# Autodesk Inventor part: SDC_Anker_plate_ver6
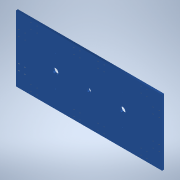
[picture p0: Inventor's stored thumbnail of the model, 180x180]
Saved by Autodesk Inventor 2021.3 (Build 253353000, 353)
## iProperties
Created: 2022-01
Part Number: SDC_Anker_plate_ver6
Material: アルミニウム 6061
Document SubType Name: Modeling
Designer: kengo
Density: 2.7 g/cm^3
Appearance: アルミニウム - フラット
Author: kengo
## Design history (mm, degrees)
sketch "スケッチ1"
  geometry: L1 (-589.671, 316.432)-(590.329, 316.432); L2 (590.329, 316.432)-(590.329, -283.568); L3 (590.329, -283.568)-(-589.671, -283.568); L4 (-589.671, -283.568)-(-589.671, 316.432); 1 further point
  constraints: 8 end point, 2 parallel, 1 horizontal, 1 perpendicular
  dimensions: "d0" = 600 distance of L3.end L1.start; "d1" = 1180 distance of L1.start L1.end
extrude "押し出し1" new body sketch "スケッチ1" distance "d2" = 15; taper "d3" = 0 deg
sketch "スケッチ4"
  geometry: L1 (-589.671, 316.432)-(-589.671, -283.568) reference; L2 (590.329, -283.568)-(590.329, 316.432) reference; L3 (-589.671, 261.432)-(590.329, 261.432); L4 (590.329, 261.432)-(590.329, -228.568); L5 (590.329, -228.568)-(-589.671, -228.568); L6 (-589.671, -228.568)-(-589.671, 261.432); L7 (590.329, 316.432)-(-589.671, 316.432) reference; L8 (-589.671, -283.568)-(590.329, -283.568) reference; L9 (-589.671, 316.432)-(590.329, 316.432); L10 (590.329, 316.432)-(590.329, -283.568); L11 (590.329, -283.568)-(-589.671, -283.568); L12 (-589.671, -283.568)-(-589.671, 316.432); 3 further points
  constraints: 16 end point, 4 parallel, 2 horizontal, 2 perpendicular, 2 point on line
  dimensions: "d58" = 490 distance between parallel lines of L5 L3; "d59" = 55 distance between parallel lines of L7 L3
extrude "押し出し2" cut sketch "スケッチ4" distance "d60" = 30; taper "d61" = 0 deg
sketch "スケッチ3" dims "d34" = 10, "d41" = 10
  geometry: L1 (-590.329, -283.568)-(-590.329, 316.432) reference; L2 (-590.329, 316.432)-(589.671, 316.432) reference; L3 (-590.329, 316.432)-(-180.344, 316.432); L4 (589.671, 261.432)-(-590.329, 261.432) reference; C1 r 3.324 at (-567.829, 228.932) reference; 25 further points
  constraints: 2 end point, 2 horizontal, 2 vertical, 1 point on line, 23 other
  dimensions: "d28" = 22.5 distance from line of L1 point (-567.829, 148.932); "d31" = 45 distance of point (-567.829, 148.932) point (-567.829, 103.932); "d38" = 45 distance of point (-567.829, 103.932) point (-522.829, 103.932); "d45" = 220 distance of point (-522.829, 148.932) point (-522.829, -71.068); "d48" = 1000 distance of point (-522.829, 148.932) point (477.171, 148.932); "d144" = 112.5 distance from line of L4 point (-567.829, 148.932)
hole "穴2" sketch "スケッチ3" diameter "d51" = 6.647; stored, may be unused: countersink angle "d55" = 90 deg, drill point angle "d57" = 118 deg; dims "d52" = 20, "d53" = 4, "d54" = 2, "d56" = 22.2
sketch "スケッチ5" dims "d83" = 10
  geometry: L1 (590.329, 261.432)-(-589.671, 261.432) reference; L2 (-589.671, 261.432)-(-589.671, -283.568) reference; 34 further points
  constraints: 2 horizontal, 1 vertical, 28 other
  dimensions: "d62" = 22.5 distance from line of L1 point (-387.171, 238.932); "d63" = 45 distance of point (-387.171, 193.932) point (-387.171, 238.932); "d64" = 45 distance of point (-342.171, 238.932) point (-342.171, 193.932); "d65" = 22.5 distance from line of L1 point (-342.171, 238.932); "d66" = 45 distance of point (-387.171, 193.932) point (-342.171, 193.932); "d69" = 45 distance of point (-387.171, 238.932) point (-342.171, 238.932); "d72" = 400 distance of point (-342.171, 238.932) point (-342.171, -161.068); "d75" = 320 distance of point (-342.171, 238.932) point (-22.171, 238.932); "d80" = 500 distance of point (-67.171, -161.068) point (432.829, -161.068); "d117" = 202.5 distance from line of L2 point (-387.171, 238.932); "d118" = 202.5 distance from line of L2 point (-387.171, 193.932)
hole "穴3" sketch "スケッチ5" diameter "d85" = 6.647; stored, may be unused: countersink angle "d89" = 90 deg, drill point angle "d91" = 118 deg; dims "d86" = 20, "d87" = 4, "d88" = 2, "d90" = 22.2
sketch "スケッチ7" dims "d101" = 10, "d108" = 10
  geometry: L1 (590.329, 261.432)-(-589.671, 261.432) reference; L2 (-589.671, 261.432)-(-589.671, -228.568) reference; L3 (-589.671, 261.432)-(-589.671, -228.568); C1 r 3.324 at (-342.171, 193.932) reference; 6 further points
  constraints: 2 end point, 1 collinear, 1 horizontal, 1 vertical, 3 other
  dimensions: "d94" = 130 distance from line of L1 point (-204.671, 131.432); "d95" = 137.5 horizontal distance of point (-204.671, 131.432) C1.centre; "d98" = 500 distance of point (-204.671, 131.432) point (295.329, 131.432); "d105" = 230 distance of point (295.329, 131.432) point (295.329, -98.568)
hole "穴4" sketch "スケッチ7" at (-204.671, 131.432), (295.329, 131.432), (295.329, -98.568), (-204.671, -98.568) diameter "d110" = 8; stored, may be unused: countersink angle "d114" = 90 deg, drill point angle "d116" = 118 deg; dims "d111" = 20, "d112" = 4, "d113" = 2, "d115" = 22.2
sketch "スケッチ8"
  geometry: L1 (-589.671, 261.432)-(590.329, 261.432) reference; L2 (590.329, -338.568)-(-589.671, -338.568); L3 (-499.671, 261.432)-(-589.671, 261.432); L4 (-589.671, 261.432)-(-589.671, -338.568); L5 (-589.671, -338.568)-(-499.671, -338.568); L6 (-499.671, -338.568)-(-499.671, 261.432); 3 further points
  constraints: 10 end point, 2 parallel, 1 horizontal, 1 perpendicular, 1 point on line
  dimensions: "d119" = 90 distance between parallel lines of L4 L6; "d142" = 600 distance of L5.end L3.start
extrude "押し出し4" cut sketch "スケッチ8" distance "d120" = 20; taper "d121" = 0 deg
sketch "スケッチ9"
  geometry: L1 (590.329, 261.432)-(-499.671, 261.432) reference; L2 (590.329, -228.568)-(590.329, 261.432) reference; 3 further points
  dimensions: "d122" = 245 distance from line of L1 point (45.329, 16.432); "d123" = 545 distance from line of L2 point (45.329, 16.432)
hole "穴5" sketch "スケッチ9" at (45.329, 16.432) diameter "d124" = 30.1; stored, may be unused: countersink angle "d128" = 90 deg, drill point angle "d130" = 118 deg; dims "d125" = 6, "d126" = 4, "d127" = 2, "d129" = 22.2
sketch "スケッチ10"
  geometry: L1 (-499.671, -228.568)-(590.329, -228.568) reference; C1 r 4 at (-204.671, 131.432) reference; C2 r 4 at (295.329, 131.432) reference; 3 further points
  dimensions: "d131" = 0 horizontal distance of C1.centre point (-204.671, 16.432); "d132" = 245 distance from line of L1 point (-204.671, 16.432); "d133" = 245 distance from line of L1 point (295.329, 16.432); "d134" = 0 horizontal distance of C2.centre point (295.329, 16.432)
hole "穴6" sketch "スケッチ10" at (-204.671, 16.432), (295.329, 16.432) diameter "d135" = 42; stored, may be unused: countersink angle "d139" = 90 deg, drill point angle "d141" = 118 deg; dims "d136" = 6, "d137" = 4, "d138" = 2, "d140" = 22.2
node "ソリッド1"
